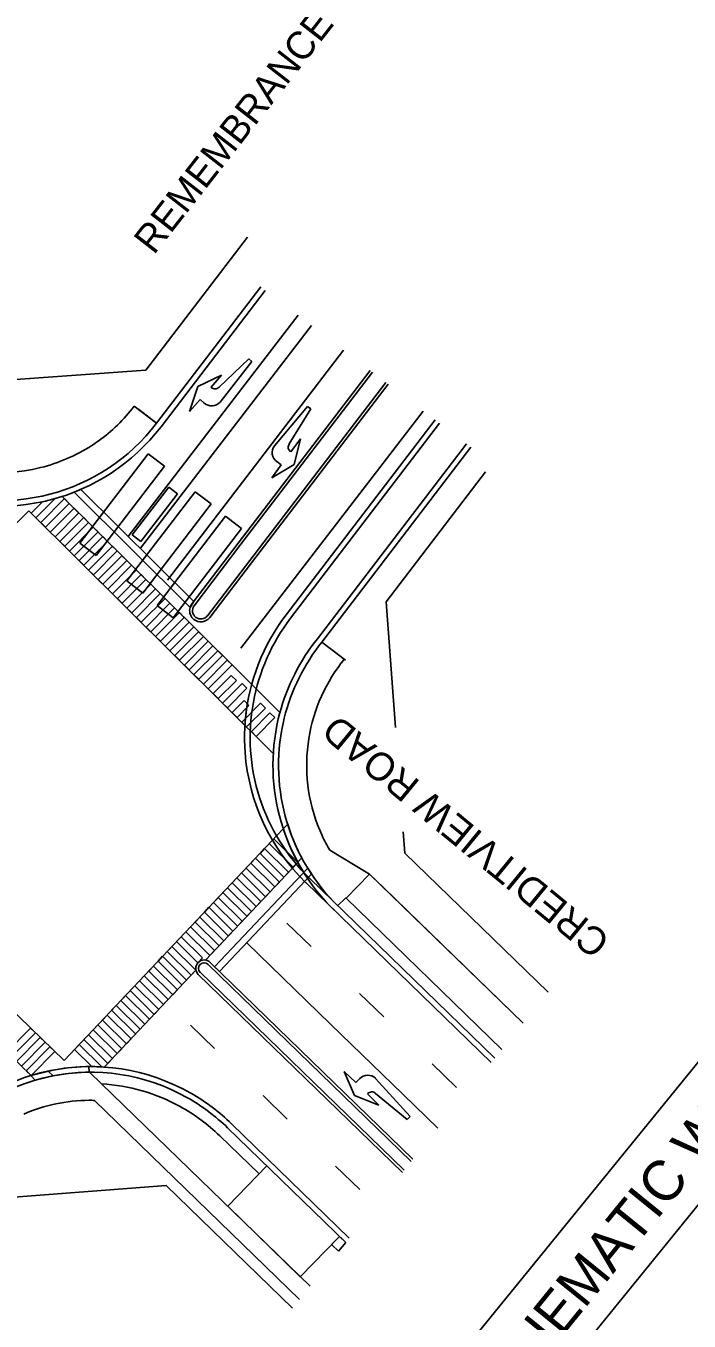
# Model space of a CAD drawing. Extents: x 592613 to 600223, y 4837996 to 4840103.
# Drawn here: x 592719.57 to 592734.31, y 4838932.93 to 4838961.75 of the extents above; entities that cross this region are included whole.
import ezdxf

# ---------------------------------------------------------------- set-up
doc = ezdxf.new("R2010")
doc.units = 0
for name, color, linetype in [('ENG_BUS-PAD', 7, 'Continuous'), ('ENG_CURB-BACK', 7, 'Continuous'), ('ENG_CURBSTOP', 7, 'Continuous'), ('ENG_EPAVT', 7, 'Continuous'), ('ENG_KILLSTRIP', 7, 'Continuous'), ('ENG_LANEWAY', 7, 'Continuous'), ('ENG_MULTI-TRAIL', 7, 'Continuous'), ('ENG_SH_KILLSTRIP', 7, 'Continuous'), ('ENG_SH_MULTI-TRAIL', 7, 'Continuous'), ('ENG_SIDEWALK', 7, 'Continuous'), ('ENG_TITLEBLOCK', 7, 'Continuous'), ('Level 11', 7, 'Continuous'), ('Level 12', 7, 'Continuous'), ('Level 32', 7, 'Continuous'), ('Level 33', 7, 'Continuous'), ('Level 43', 7, 'Continuous'), ('PMK_LANE', 7, 'Continuous'), ('PMK_LANE_3-6', 7, 'Continuous'), ('ROW_ENG_ROW', 7, 'Continuous'), ('ROW_ENG_ROW BO', 7, 'Continuous')]:
    doc.layers.add(name, color=color, linetype=linetype)

msp = doc.modelspace()

# ---------------------------------------------------------------- linework, layer by layer
at = {"layer": 'ENG_BUS-PAD'}
for p, q in [((592724.924, 4838936.386), (592724.053, 4838935.49)), ((592725.667, 4838933.922), (592724.053, 4838935.49)), ((592726.538, 4838934.818), (592725.667, 4838933.922))]:
    msp.add_line(p, q, dxfattribs=at)
at = {"layer": 'ENG_CURB-BACK'}
for p, q in [((592724.788, 4838955.943), (592722.472, 4838952.91)), ((592727.271, 4838954.046), (592724.326, 4838950.189)), ((592728.762, 4838952.909), (592725.45, 4838948.571)), ((592729.457, 4838952.378), (592726.145, 4838948.04)), ((592726.145, 4838948.04), (592726.082, 4838947.957)), ((592729.99, 4838938.785), (592725.879, 4838942.778)), ((592728.132, 4838936.486), (592723.618, 4838940.871)), ((592727.974, 4838936.291), (592723.441, 4838940.694)), ((592726.676, 4838934.684), (592724.051, 4838937.234))]:
    msp.add_line(p, q, dxfattribs=at)
for centre, radius, start, end in [((592718.995, 4838955.565), 4.375, 246.6005, 322.6377), ((592728.927, 4838945.916), 4.375, 142.6377, 169.6205), ((592729.559, 4838945.302), 4.375, 142.6377, 167.7306), ((592728.927, 4838945.916), 4.375, 169.6205, 225.8289), ((592729.559, 4838945.302), 4.375, 167.7306, 225.8289), ((592723.53, 4838940.782), 0.125, 45.2459, 225.2459), ((592721.003, 4838934.096), 4.375, 60.4988, 142.6377), ((592721.003, 4838934.096), 4.375, 45.8289, 60.4988)]:
    msp.add_arc(centre, radius, start, end, dxfattribs=at)
at = {"layer": 'ENG_CURBSTOP'}
for p, q in [((592725.387, 4838943.987), (592725.288, 4838943.887)), ((592725.701, 4838943.239), (592725.484, 4838943.02)), ((592720.171, 4838938.391), (592720.062, 4838938.497)), ((592720.984, 4838938.471), (592720.962, 4838938.596))]:
    msp.add_line(p, q, dxfattribs=at)
for points in [[(592725.701, 4838943.239), (592725.609, 4838943.146), (592725.493, 4838943.374), (592725.413, 4838943.554), (592725.288, 4838943.888), (592725.387, 4838943.987), (592725.473, 4838943.739), (592725.599, 4838943.442), (592725.642, 4838943.347)], [(592720.984, 4838938.471), (592720.73, 4838938.463), (592720.445, 4838938.435), (592720.202, 4838938.397), (592719.775, 4838938.294), (592719.679, 4838938.395), (592720.174, 4838938.519), (592720.306, 4838938.542), (592720.42, 4838938.558), (592720.586, 4838938.577), (592720.764, 4838938.59), (592720.901, 4838938.595), (592720.962, 4838938.596)]]:
    msp.add_lwpolyline(points, close=True, dxfattribs=at)
at = {"layer": 'ENG_EPAVT'}
for p, q in [((592724.887, 4838955.867), (592722.571, 4838952.834)), ((592727.222, 4838954.084), (592724.289, 4838950.243)), ((592727.569, 4838953.819), (592724.543, 4838949.856)), ((592727.619, 4838953.781), (592724.583, 4838949.804)), ((592728.662, 4838952.984), (592725.351, 4838948.647)), ((592729.358, 4838952.453), (592726.046, 4838948.116)), ((592724.289, 4838950.243), (592723.262, 4838948.899)), ((592724.325, 4838950.188), (592723.304, 4838948.851)), ((592724.543, 4838949.856), (592723.607, 4838948.629)), ((592724.581, 4838949.803), (592723.656, 4838948.591)), ((592726.046, 4838948.116), (592725.983, 4838948.033)), ((592729.911, 4838938.687), (592725.792, 4838942.689)), ((592728.171, 4838936.535), (592723.662, 4838940.916)), ((592727.935, 4838936.242), (592723.398, 4838940.649)), ((592726.755, 4838934.782), (592724.138, 4838937.324))]:
    msp.add_line(p, q, dxfattribs=at)
for centre, radius, start, end in [((592718.995, 4838955.565), 4.5, 246.1583, 322.6377), ((592723.457, 4838948.742), 0.25, 141.1016, 322.9443), ((592723.457, 4838948.742), 0.187, 144.4115, 322.9443), ((592728.927, 4838945.916), 4.5, 142.6377, 174.56), ((592729.559, 4838945.302), 4.5, 142.6377, 166.783), ((592728.927, 4838945.916), 4.5, 170.2582, 184.2333), ((592729.559, 4838945.302), 4.5, 166.783, 225.8289), ((592728.927, 4838945.916), 4.5, 184.2333, 225.8289), ((592723.53, 4838940.782), 0.187, 45.2459, 225.2459), ((592721.003, 4838934.096), 4.5, 60.2342, 142.6377), ((592721.003, 4838934.096), 4.125, 61.0962, 86.5779), ((592721.003, 4838934.096), 4.5, 45.8289, 60.2342), ((592721.003, 4838934.096), 4.125, 45.8289, 61.0962)]:
    msp.add_arc(centre, radius, start, end, dxfattribs=at)
at = {"layer": 'ENG_KILLSTRIP'}
for p, q in [((592730.147, 4838938.98), (592726.685, 4838942.344)), ((592724.75, 4838936.207), (592723.877, 4838937.055)), ((592726.518, 4838934.489), (592726.363, 4838934.639))]:
    msp.add_line(p, q, dxfattribs=at)
at = {"layer": 'ENG_LANEWAY'}
for p, q in [((592725.62, 4838955.313), (592721.841, 4838950.391)), ((592725.917, 4838955.084), (592722.114, 4838950.13)), ((592728.396, 4838953.181), (592724.344, 4838947.903))]:
    msp.add_line(p, q, dxfattribs=at)
at = {"layer": 'ENG_MULTI-TRAIL'}
for p, q in [((592727.208, 4838942.881), (592726.685, 4838942.343)), ((592730.621, 4838939.566), (592727.208, 4838942.881))]:
    msp.add_line(p, q, dxfattribs=at)
at = {"layer": 'ENG_SH_KILLSTRIP'}
for p, q in [((592726.538, 4838934.818), (592726.363, 4838934.639)), ((592726.676, 4838934.684), (592726.538, 4838934.818)), ((592726.363, 4838934.639), (592726.518, 4838934.489)), ((592726.518, 4838934.489), (592726.676, 4838934.684))]:
    msp.add_line(p, q, dxfattribs=at)
at = {"layer": 'ENG_SH_MULTI-TRAIL'}
msp.add_lwpolyline([(592730.621, 4838939.566), (592727.525, 4838942.573), (592727.208, 4838942.881), (592726.685, 4838942.343), (592726.685, 4838942.344), (592730.147, 4838938.98)], dxfattribs=at)
at = {"layer": 'ENG_SIDEWALK'}
for p, q in [((592722.472, 4838952.911), (592721.975, 4838953.29)), ((592722.472, 4838952.91), (592722.075, 4838953.214)), ((592726.671, 4838947.639), (592726.145, 4838948.04)), ((592726.543, 4838947.737), (592726.145, 4838948.04)), ((592726.579, 4838947.578), (592726.642, 4838947.661)), ((592727.208, 4838942.881), (592726.322, 4838943.409)), ((592726.676, 4838942.352), (592726.495, 4838942.17)), ((592721.249, 4838938.214), (592720.984, 4838938.471)), ((592725.887, 4838933.708), (592721.249, 4838938.214)), ((592725.65, 4838933.415), (592721.09, 4838937.845))]:
    msp.add_line(p, q, dxfattribs=at)
for centre, start, end in [((592718.995, 4838955.565), 305.4959, 322.6377), ((592718.995, 4838955.565), 239.233, 283.8878), ((592718.995, 4838955.565), 283.8878, 302.8741), ((592718.995, 4838955.565), 302.8741, 305.4959), ((592729.559, 4838945.302), 142.6377, 172.7872), ((592729.559, 4838945.302), 172.7872, 204.683), ((592729.559, 4838945.302), 204.683, 210.3244), ((592721.003, 4838934.096), 90.4558, 113.33), ((592721.003, 4838934.096), 88.6623, 90.4558)]:
    msp.add_arc(centre, 3.75, start, end, dxfattribs=at)
at = {"layer": 'ENG_TITLEBLOCK'}
for p, q in [((592720.007, 4838920.852), (592747.546, 4838954.746)), ((592721.564, 4838919.587), (592749.103, 4838953.481))]:
    msp.add_line(p, q, dxfattribs=at)
at = {"layer": 'Level 11'}
for p, q in [((592722.288, 4838952.228), (592720.769, 4838950.242)), ((592722.645, 4838951.954), (592722.288, 4838952.228)), ((592721.126, 4838949.969), (592722.645, 4838951.954)), ((592722.742, 4838951.49), (592721.929, 4838950.426)), ((592722.934, 4838951.343), (592722.742, 4838951.49)), ((592723.327, 4838951.388), (592721.808, 4838949.402)), ((592722.12, 4838950.28), (592722.934, 4838951.343)), ((592723.684, 4838951.115), (592723.327, 4838951.388)), ((592722.165, 4838949.129), (592723.684, 4838951.115)), ((592724.003, 4838950.842), (592722.484, 4838948.856)), ((592724.36, 4838950.569), (592724.003, 4838950.842)), ((592721.929, 4838950.426), (592722.12, 4838950.28)), ((592722.841, 4838948.583), (592724.36, 4838950.569)), ((592720.769, 4838950.242), (592721.126, 4838949.969)), ((592721.808, 4838949.402), (592722.165, 4838949.129)), ((592722.484, 4838948.856), (592722.841, 4838948.583))]:
    msp.add_line(p, q, dxfattribs=at)
at = {"layer": 'Level 12'}
for p, q in [((592723.861, 4838953.714), (592724.523, 4838954.343)), ((592724.523, 4838954.343), (592724.591, 4838954.282)), ((592724.591, 4838954.282), (592723.885, 4838953.38)), ((592723.392, 4838953.725), (592723.918, 4838953.977)), ((592723.918, 4838953.977), (592723.679, 4838953.709)), ((592723.201, 4838953.174), (592723.392, 4838953.725)), ((592723.44, 4838953.442), (592723.201, 4838953.174)), ((592723.532, 4838953.36), (592723.44, 4838953.442)), ((592725.825, 4838953.285), (592725.09, 4838952.406)), ((592725.423, 4838952.452), (592725.899, 4838953.231)), ((592725.899, 4838953.231), (592725.825, 4838953.285)), ((592725.668, 4838952.563), (592725.456, 4838952.273)), ((592725.532, 4838951.996), (592725.668, 4838952.563)), ((592725.145, 4838952.057), (592725.245, 4838951.984)), ((592725.033, 4838951.694), (592725.532, 4838951.996)), ((592725.245, 4838951.984), (592725.033, 4838951.694)), ((592726.901, 4838938.241), (592726.644, 4838938.49)), ((592726.644, 4838938.49), (592726.874, 4838937.955)), ((592726.987, 4838938.329), (592726.901, 4838938.241)), ((592728.11, 4838937.486), (592727.341, 4838938.335)), ((592726.874, 4838937.955), (592727.416, 4838937.742)), ((592727.416, 4838937.742), (592727.159, 4838937.991)), ((592727.341, 4838937.999), (592728.046, 4838937.421)), ((592728.046, 4838937.421), (592728.11, 4838937.486))]:
    msp.add_line(p, q, dxfattribs=at)
for centre, radius, start, end in [((592723.768, 4838953.798), 0.125, 228.2469, 318.2706), ((592723.699, 4838953.546), 0.25, 228.242, 318.2642), ((592725.292, 4838952.259), 0.25, 143.8506, 233.8728), ((592725.524, 4838952.378), 0.125, 143.8443, 233.8679), ((592727.167, 4838938.156), 0.25, 45.9051, 135.9273), ((592727.254, 4838937.909), 0.125, 45.8987, 135.9224)]:
    msp.add_arc(centre, radius, start, end, dxfattribs=at)
at = {"layer": 'PMK_LANE'}
for p, q in [((592726.626, 4838954.54), (592722.715, 4838949.418)), ((592719.935, 4838951.165), (592719.684, 4838950.913)), ((592719.791, 4838950.807), (592720.215, 4838951.234)), ((592720.426, 4838951.233), (592719.897, 4838950.701)), ((592720.376, 4838951.283), (592724.217, 4838947.467)), ((592720.532, 4838951.127), (592720.426, 4838951.233)), ((592720.637, 4838951.376), (592723.217, 4838948.813)), ((592720.787, 4838951.438), (592723.297, 4838948.945)), ((592719.631, 4838950.965), (592714.649, 4838945.946)), ((592719.631, 4838950.965), (592725.067, 4838945.566)), ((592719.684, 4838950.913), (592719.791, 4838950.807)), ((592720.003, 4838950.596), (592720.532, 4838951.127)), ((592720.639, 4838951.022), (592720.11, 4838950.49)), ((592720.216, 4838950.384), (592720.745, 4838950.916)), ((592720.745, 4838950.916), (592720.639, 4838951.022)), ((592719.897, 4838950.701), (592720.003, 4838950.596)), ((592720.852, 4838950.81), (592720.323, 4838950.279)), ((592720.429, 4838950.173), (592720.958, 4838950.704)), ((592721.065, 4838950.599), (592720.535, 4838950.067)), ((592720.958, 4838950.704), (592720.852, 4838950.81)), ((592721.171, 4838950.493), (592721.065, 4838950.599)), ((592720.11, 4838950.49), (592720.216, 4838950.384)), ((592720.642, 4838949.961), (592721.171, 4838950.493)), ((592721.277, 4838950.387), (592720.748, 4838949.856)), ((592721.384, 4838950.282), (592721.277, 4838950.387)), ((592720.323, 4838950.279), (592720.429, 4838950.173)), ((592720.535, 4838950.067), (592720.642, 4838949.961)), ((592720.855, 4838949.75), (592721.384, 4838950.282)), ((592721.49, 4838950.176), (592720.961, 4838949.644)), ((592721.068, 4838949.539), (592721.597, 4838950.07)), ((592721.597, 4838950.07), (592721.49, 4838950.176)), ((592720.748, 4838949.856), (592720.855, 4838949.75)), ((592721.703, 4838949.964), (592721.174, 4838949.433)), ((592721.28, 4838949.327), (592721.81, 4838949.859)), ((592721.916, 4838949.753), (592721.387, 4838949.222)), ((592721.81, 4838949.859), (592721.703, 4838949.964)), ((592722.022, 4838949.647), (592721.916, 4838949.753)), ((592720.961, 4838949.644), (592721.068, 4838949.539)), ((592721.174, 4838949.433), (592721.28, 4838949.327)), ((592721.493, 4838949.116), (592722.022, 4838949.647)), ((592722.129, 4838949.542), (592721.6, 4838949.01)), ((592721.706, 4838948.904), (592722.235, 4838949.436)), ((592722.235, 4838949.436), (592722.129, 4838949.542)), ((592721.387, 4838949.222), (592721.493, 4838949.116)), ((592722.342, 4838949.33), (592721.813, 4838948.799)), ((592721.919, 4838948.693), (592722.448, 4838949.225)), ((592722.448, 4838949.225), (592722.342, 4838949.33)), ((592721.6, 4838949.01), (592721.706, 4838948.904)), ((592722.555, 4838949.119), (592722.025, 4838948.587)), ((592722.132, 4838948.482), (592722.661, 4838949.013)), ((592722.767, 4838948.907), (592722.238, 4838948.376)), ((592722.661, 4838949.013), (592722.555, 4838949.119)), ((592722.874, 4838948.802), (592722.767, 4838948.907)), ((592721.813, 4838948.799), (592721.919, 4838948.693)), ((592722.025, 4838948.587), (592722.132, 4838948.482)), ((592722.345, 4838948.27), (592722.874, 4838948.802)), ((592722.98, 4838948.696), (592722.451, 4838948.164)), ((592722.558, 4838948.059), (592723.087, 4838948.59)), ((592723.087, 4838948.59), (592722.98, 4838948.696)), ((592722.238, 4838948.376), (592722.345, 4838948.27)), ((592723.193, 4838948.485), (592722.664, 4838947.953)), ((592722.77, 4838947.847), (592723.299, 4838948.379)), ((592723.299, 4838948.379), (592723.193, 4838948.485)), ((592722.451, 4838948.164), (592722.558, 4838948.059)), ((592723.406, 4838948.273), (592722.877, 4838947.742)), ((592722.983, 4838947.636), (592723.512, 4838948.167)), ((592723.619, 4838948.062), (592723.09, 4838947.53)), ((592723.512, 4838948.167), (592723.406, 4838948.273)), ((592723.725, 4838947.956), (592723.619, 4838948.062)), ((592722.664, 4838947.953), (592722.77, 4838947.847)), ((592722.877, 4838947.742), (592722.983, 4838947.636)), ((592723.196, 4838947.424), (592723.725, 4838947.956)), ((592723.832, 4838947.85), (592723.303, 4838947.319)), ((592723.409, 4838947.213), (592723.938, 4838947.745)), ((592723.938, 4838947.745), (592723.832, 4838947.85)), ((592723.09, 4838947.53), (592723.196, 4838947.424)), ((592724.044, 4838947.639), (592723.515, 4838947.107)), ((592723.622, 4838947.002), (592724.151, 4838947.533)), ((592724.151, 4838947.533), (592724.044, 4838947.639)), ((592724.217, 4838947.467), (592725.215, 4838946.476)), ((592723.303, 4838947.319), (592723.409, 4838947.213)), ((592724.132, 4838947.301), (592723.728, 4838946.896)), ((592723.842, 4838946.783), (592724.246, 4838947.188)), ((592724.246, 4838947.188), (592724.132, 4838947.301)), ((592723.515, 4838947.107), (592723.622, 4838947.002)), ((592723.728, 4838946.896), (592723.842, 4838946.783)), ((592724.373, 4838947.118), (592723.941, 4838946.685)), ((592724.048, 4838946.579), (592724.479, 4838947.013)), ((592724.479, 4838947.013), (592724.373, 4838947.118)), ((592723.941, 4838946.685), (592724.048, 4838946.579)), ((592724.418, 4838946.739), (592724.154, 4838946.473)), ((592724.26, 4838946.367), (592724.525, 4838946.633)), ((592724.783, 4838946.68), (592724.367, 4838946.262)), ((592724.525, 4838946.633), (592724.418, 4838946.739)), ((592724.473, 4838946.156), (592724.89, 4838946.574)), ((592724.89, 4838946.574), (592724.783, 4838946.68)), ((592724.154, 4838946.473), (592724.26, 4838946.367)), ((592724.367, 4838946.262), (592724.473, 4838946.156)), ((592724.993, 4838946.465), (592724.58, 4838946.05)), ((592724.686, 4838945.944), (592725.099, 4838946.36)), ((592725.099, 4838946.36), (592724.993, 4838946.465)), ((592724.58, 4838946.05), (592724.686, 4838945.944)), ((592714.928, 4838944.059), (592720.415, 4838938.73)), ((592720.415, 4838938.73), (592725.288, 4838943.887)), ((592725.08, 4838943.667), (592724.977, 4838943.558)), ((592725.613, 4838943.14), (592725.08, 4838943.667)), ((592724.874, 4838943.449), (592724.771, 4838943.34)), ((592725.407, 4838942.921), (592724.874, 4838943.449)), ((592724.977, 4838943.558), (592725.51, 4838943.03)), ((592714.776, 4838943.161), (592719.681, 4838938.398)), ((592723.561, 4838940.967), (592725.613, 4838943.14)), ((592724.668, 4838943.231), (592724.565, 4838943.122)), ((592724.565, 4838943.122), (592725.098, 4838942.594)), ((592725.201, 4838942.703), (592724.668, 4838943.231)), ((592724.771, 4838943.34), (592725.304, 4838942.812)), ((592725.51, 4838943.03), (592725.613, 4838943.14)), ((592723.763, 4838940.817), (592725.834, 4838943.009)), ((592723.871, 4838940.713), (592725.917, 4838942.879)), ((592724.461, 4838943.013), (592724.358, 4838942.904)), ((592724.358, 4838942.904), (592724.892, 4838942.376)), ((592724.995, 4838942.485), (592724.461, 4838943.013)), ((592725.304, 4838942.812), (592725.407, 4838942.921)), ((592724.049, 4838942.577), (592723.946, 4838942.467)), ((592724.583, 4838942.049), (592724.049, 4838942.577)), ((592724.255, 4838942.795), (592724.152, 4838942.686)), ((592724.152, 4838942.686), (592724.686, 4838942.158)), ((592724.789, 4838942.267), (592724.255, 4838942.795)), ((592725.098, 4838942.594), (592725.201, 4838942.703)), ((592723.843, 4838942.358), (592723.74, 4838942.249)), ((592723.74, 4838942.249), (592724.273, 4838941.722)), ((592724.377, 4838941.831), (592723.843, 4838942.358)), ((592723.946, 4838942.467), (592724.48, 4838941.94)), ((592724.686, 4838942.158), (592724.789, 4838942.267)), ((592724.892, 4838942.376), (592724.995, 4838942.485)), ((592723.637, 4838942.14), (592723.534, 4838942.031)), ((592723.534, 4838942.031), (592724.067, 4838941.504)), ((592724.17, 4838941.613), (592723.637, 4838942.14)), ((592724.48, 4838941.94), (592724.583, 4838942.049)), ((592723.225, 4838941.704), (592723.122, 4838941.595)), ((592723.758, 4838941.176), (592723.225, 4838941.704)), ((592723.431, 4838941.922), (592723.328, 4838941.813)), ((592723.328, 4838941.813), (592723.861, 4838941.285)), ((592723.964, 4838941.395), (592723.431, 4838941.922)), ((592724.273, 4838941.722), (592724.377, 4838941.831)), ((592723.019, 4838941.486), (592722.916, 4838941.377)), ((592722.916, 4838941.377), (592723.391, 4838940.907)), ((592723.494, 4838941.016), (592723.019, 4838941.486)), ((592723.122, 4838941.595), (592723.655, 4838941.067)), ((592723.861, 4838941.285), (592723.964, 4838941.395)), ((592724.067, 4838941.504), (592724.17, 4838941.613)), ((592722.813, 4838941.268), (592722.71, 4838941.159)), ((592722.71, 4838941.159), (592723.243, 4838940.631)), ((592723.346, 4838940.74), (592722.813, 4838941.268)), ((592723.655, 4838941.067), (592723.758, 4838941.176)), ((592726.341, 4838939.541), (592724.475, 4838941.353)), ((592722.401, 4838940.832), (592722.298, 4838940.722)), ((592722.934, 4838940.304), (592722.401, 4838940.832)), ((592722.607, 4838941.05), (592722.504, 4838940.941)), ((592722.504, 4838940.941), (592723.037, 4838940.413)), ((592723.14, 4838940.522), (592722.607, 4838941.05)), ((592723.391, 4838940.907), (592723.494, 4838941.016)), ((592721.31, 4838938.586), (592723.347, 4838940.741)), ((592722.195, 4838940.613), (592722.092, 4838940.504)), ((592722.092, 4838940.504), (592722.625, 4838939.977)), ((592722.728, 4838940.086), (592722.195, 4838940.613)), ((592722.298, 4838940.722), (592722.831, 4838940.195)), ((592723.037, 4838940.413), (592723.14, 4838940.522)), ((592723.243, 4838940.631), (592723.346, 4838940.74)), ((592721.988, 4838940.395), (592721.885, 4838940.286)), ((592721.885, 4838940.286), (592722.419, 4838939.759)), ((592722.522, 4838939.868), (592721.988, 4838940.395)), ((592722.831, 4838940.195), (592722.934, 4838940.304)), ((592721.576, 4838939.959), (592721.473, 4838939.85)), ((592722.11, 4838939.431), (592721.576, 4838939.959)), ((592721.782, 4838940.177), (592721.679, 4838940.068)), ((592721.679, 4838940.068), (592722.213, 4838939.54)), ((592722.316, 4838939.65), (592721.782, 4838940.177)), ((592721.37, 4838939.741), (592721.267, 4838939.632)), ((592721.904, 4838939.213), (592721.37, 4838939.741)), ((592721.473, 4838939.85), (592722.007, 4838939.322)), ((592722.213, 4838939.54), (592722.316, 4838939.65)), ((592722.419, 4838939.759), (592722.522, 4838939.868)), ((592719.67, 4838939.454), (592719.143, 4838938.92)), ((592719.25, 4838938.816), (592719.777, 4838939.349)), ((592719.777, 4838939.349), (592719.67, 4838939.454)), ((592721.164, 4838939.523), (592721.061, 4838939.414)), ((592721.061, 4838939.414), (592721.594, 4838938.886)), ((592721.697, 4838938.995), (592721.164, 4838939.523)), ((592721.267, 4838939.632), (592721.801, 4838939.104)), ((592722.007, 4838939.322), (592722.11, 4838939.431)), ((592727.955, 4838937.973), (592726.341, 4838939.541)), ((592719.885, 4838939.245), (592719.358, 4838938.711)), ((592719.466, 4838938.607), (592719.993, 4838939.14)), ((592719.993, 4838939.14), (592719.885, 4838939.245)), ((592720.752, 4838939.087), (592720.649, 4838938.977)), ((592721.255, 4838938.589), (592720.752, 4838939.087)), ((592720.958, 4838939.305), (592720.855, 4838939.196)), ((592720.855, 4838939.196), (592721.388, 4838938.668)), ((592721.491, 4838938.777), (592720.958, 4838939.305)), ((592721.801, 4838939.104), (592721.904, 4838939.213)), ((592720.1, 4838939.036), (592719.573, 4838938.502)), ((592719.681, 4838938.398), (592720.208, 4838938.931)), ((592720.208, 4838938.931), (592720.1, 4838939.036)), ((592720.649, 4838938.977), (592721.035, 4838938.596)), ((592721.388, 4838938.668), (592721.491, 4838938.777)), ((592721.594, 4838938.886), (592721.697, 4838938.995)), ((592719.573, 4838938.502), (592719.681, 4838938.398)), ((592728.727, 4838937.223), (592727.955, 4838937.973))]:
    msp.add_line(p, q, dxfattribs=at)
for points in [[(592720.151, 4838951.216), (592720.151, 4838951.214), (592720.08, 4838951.198)], [(592722.625, 4838939.977), (592722.686, 4838940.042), (592722.728, 4838940.086)]]:
    msp.add_lwpolyline(points, dxfattribs=at)
for points in [[(592720.637, 4838951.376), (592720.787, 4838951.438), (592723.297, 4838948.945), (592723.217, 4838948.813)], [(592725.834, 4838943.009), (592725.917, 4838942.879), (592723.871, 4838940.713), (592723.763, 4838940.817)]]:
    msp.add_lwpolyline(points, close=True, dxfattribs=at)
for centre, start, end in [((592718.995, 4838955.565), 282.0553, 283.9602), ((592718.995, 4838955.565), 284.8874, 285.7389), ((592721.003, 4838934.096), 86.7865, 89.5933)]:
    msp.add_arc(centre, 4.5, start, end, dxfattribs=at)
at = {"layer": 'PMK_LANE_3-6'}
for p, q in [((592725.908, 4838941.268), (592725.37, 4838941.791)), ((592727.522, 4838939.7), (592726.984, 4838940.223)), ((592723.224, 4838939.519), (592723.762, 4838938.996)), ((592729.136, 4838938.132), (592728.598, 4838938.655)), ((592724.838, 4838937.951), (592725.376, 4838937.428)), ((592726.452, 4838936.383), (592726.99, 4838935.86))]:
    msp.add_line(p, q, dxfattribs=at)
at = {"layer": 'ROW_ENG_ROW'}
for p, q in [((592717.284, 4838953.742), (592722.233, 4838954.089)), ((592727.781, 4838946.139), (592727.574, 4838948.935)), ((592727.988, 4838943.344), (592727.952, 4838943.82)), ((592731.173, 4838940.249), (592727.988, 4838943.344)), ((592722.682, 4838935.95), (592717.554, 4838935.554)), ((592725.492, 4838933.22), (592722.682, 4838935.95))]:
    msp.add_line(p, q, dxfattribs=at)
at = {"layer": 'ROW_ENG_ROW BO'}
for p, q in [((592722.233, 4838954.089), (592724.493, 4838957.049)), ((592727.574, 4838948.935), (592729.782, 4838951.828))]:
    msp.add_line(p, q, dxfattribs=at)

# ---------------------------------------------------------------- texts
at = {"layer": 'Level 32'}
msp.add_text('CREDITVIEW ROAD', height=0.625, rotation=140.5921, dxfattribs=at).set_placement((592732.591, 4838941.447))
at = {"layer": 'Level 33'}
msp.add_text('REMEMBRANCE ROAD', height=0.61958, rotation=52.007, dxfattribs=at).set_placement((592722.413, 4838956.64))
at = {"layer": 'Level 43'}
msp.add_text('SCHEMATIC WIRING DIAGRAM', height=0.9, rotation=50.9062, dxfattribs=at).set_placement((592729.874, 4838930.598))

doc.saveas('drawing.dxf')
